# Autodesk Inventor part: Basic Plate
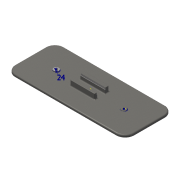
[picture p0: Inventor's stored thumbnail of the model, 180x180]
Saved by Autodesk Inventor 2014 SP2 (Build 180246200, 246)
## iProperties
Created: 2016-02
Part Number: Basic Plate
Material: Steel, Cast
Document SubType Name: Modeling
Designer: User
Density: 7.85 g/cm^3
Appearance: Steel - Cast
Author: User
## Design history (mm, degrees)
sketch "Sketch1"
  geometry: L1 (-270, -110)-(270, -110); L2 (270, -110)-(270, 110); L3 (270, 110)-(-270, 110); L4 (-270, 110)-(-270, -110); L5 (-270, -110)-(270, 110); L6 (270, -110)-(-270, 110); 1 further point
  constraints: 12 end point, 2 midpoint, 2 parallel, 1 horizontal, 1 perpendicular
  dimensions: "d0" = 540 distance of L3.end L2.end; "d1" = 220 distance of L2.end L1.end
extrude "Extrusion1" new body sketch "Sketch1" distance "d2" = 10; taper "d3" = 0 deg
fillet "Fillet1" dims "d4" = 40
fillet "Fillet2" dims "d5" = 5
sketch "Sketch2"
  geometry: C1 r 10 at (-230, 70); C2 r 10 at (-230, -70); C3 r 10 at (230, -70); C4 r 10 at (230, 70); A1 r 40 centre (-230, -70) between (-270, -70) and (-230, -110) reference; A2 r 40 centre (230, -70) between (230, -110) and (270, -70) reference; A3 r 40 centre (230, 70) between (270, 70) and (230, 110) reference; A4 r 40 centre (-230, 70) between (-230, 110) and (-270, 70) reference; 1 further point
  constraints: 4 centre point, 4 coincident, 3 equal radius
  dimensions: "d6" = 20 diameter of C1
extrude "Extrusion2" join sketch "Sketch2" distance "d7" = 16; taper "d8" = 0 deg
fillet "Fillet3" dims "d9" = 5
fillet "Fillet4" dims "d10" = 2
sketch "Sketch3"
  geometry: L1 (-265, -70)-(-265, 70) reference; L2 (-153.5, 0)-(153.5, 0); 4 further points
  constraints: 3 coincident, 2 end point, 1 midpoint, 1 perpendicular
  dimensions: "d11" = 307 distance of L2.start L2.end
hole "Hole1" sketch "Sketch3" at (-153.5, 0), (153.5, 0) diameter "d12" = 12; stored, may be unused: countersink angle "d16" = 90 deg, drill point angle "d18" = 118 deg; dims "d13" = 6, "d14" = 4, "d15" = 2, "d17" = 8
sketch "Sketch4"
  geometry: C1 r 6 at (-153.5, 0) reference; C2 r 6 at (153.5, 0) reference; C3 r 12 at (-153.5, 0); C4 r 12 at (153.5, 0); 1 further point
  constraints: 2 centre point, 2 coincident, 1 equal radius
  dimensions: "d19" = 24 diameter of C3
extrude "Extrusion3" join sketch "Sketch4" distance "d20" = 4; taper "d21" = 0 deg
extrude "Extrusion7" join sketch "Sketch4" distance "d38" = 2; taper "d39" = 0 deg
fillet "Fillet5" dims "d22" = 2
sketch "Sketch5"
  geometry: L1 (50.5, -29.308)-(-61.5, -29.308); L2 (-61.5, -29.308)-(-61.5, 35.692); L3 (-61.5, 35.692)-(50.5, 35.692); L4 (50.5, 35.692)-(50.5, -29.308); L5 (50.5, -29.308)-(-61.5, 35.692); L6 (-61.5, -29.308)-(50.5, 35.692); C1 r 14 at (-153.5, 0) reference; 1 further point
  constraints: 12 end point, 2 parallel, 1 horizontal, 1 perpendicular, 1 point on line
  dimensions: "d23" = 112 distance of L2.end L3.end; "d24" = 65 distance of L1.end L2.end; "d33" = 92 distance from line of L2 C1.centre
extrude "Extrusion4" join sketch "Sketch5" distance "d25" = 24; taper "d26" = 0 deg
fillet "Fillet6" dims "d27" = 4
sketch "Sketch6"
  geometry: L1 (-61.5, 35.692)-(-61.5, -29.308) reference; L2 (61.5, -20)-(-61.5, -20); L3 (-61.5, -20)-(-61.5, 20); L4 (-61.5, 20)-(61.5, 20); L5 (61.5, 20)-(61.5, -20); L6 (61.5, -20)-(-61.5, 20); L7 (-61.5, -20)-(61.5, 20); 1 further point
  constraints: 12 end point, 2 midpoint, 2 parallel, 1 horizontal, 1 perpendicular, 1 point on line
  dimensions: "d28" = 40 distance of L2.end L3.end
extrude "Extrusion5" cut sketch "Sketch6" distance "d29" = 8; taper "d30" = 0 deg
fillet "Fillet7" dims "d31" = 4
fillet "Fillet8" dims "d32" = 2
sketch "Sketch7"
  geometry: L1 (230, -105)-(-230, -105) reference; L2 (265, 70)-(265, -70) reference; L3 (-230, 105)-(230, 105) reference; L4 (-265, -70)-(-265, 70) reference; L5 (54.5, -33.308)-(54.5, 39.692) reference; L6 (-65.5, -33.308)-(54.5, -33.308) reference; L7 (-65.5, 39.692)-(-65.5, -33.308) reference; L8 (54.5, 39.692)-(-65.5, 39.692) reference; L9 (-65.5, 18)-(54.5, 18); L10 (54.5, 18)-(54.5, -18); L11 (54.5, -18)-(-65.5, -18); L12 (-65.5, -18)-(-65.5, 18); C1 r 14 at (-153.5, 0) reference; A1 r 35 centre (230, -70) between (230, -105) and (265, -70) reference; A2 r 35 centre (230, 70) between (265, 70) and (230, 105) reference; A3 r 35 centre (-230, 70) between (-230, 105) and (-265, 70) reference; A4 r 35 centre (-230, -70) between (-265, -70) and (-230, -105) reference; 2 further points
  constraints: 8 end point, 2 parallel, 2 point on line, 1 horizontal, 1 horizontal alignment, 1 midpoint, 1 perpendicular
  dimensions: "d34" = 36 distance between parallel lines of L11 L9
extrude "Extrusion6" cut sketch "Sketch7" stored distance "d35" = 12; taper "d36" = 0 deg
fillet "Fillet9" dims "d37" = 4
body "Solid1"
node "Projected Loop1"
